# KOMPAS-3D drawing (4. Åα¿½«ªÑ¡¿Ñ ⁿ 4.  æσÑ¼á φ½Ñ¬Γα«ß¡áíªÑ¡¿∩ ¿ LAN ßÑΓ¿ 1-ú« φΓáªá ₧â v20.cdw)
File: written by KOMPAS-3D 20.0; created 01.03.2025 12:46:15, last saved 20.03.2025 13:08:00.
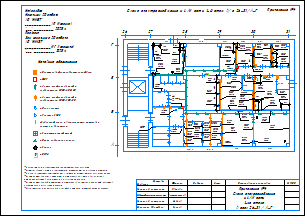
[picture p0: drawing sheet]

Sheet 1: A4, landscape

Document properties: Автор: user; Полное имя файла: \\Storage\20 Отдел\Мои документы\Крашенинников Е\ТЗ 1й этаж юг\готово\4. Приложение № 4.  Схема электроснабжения и LAN сети 1-го этажа ЮГ v20.cdw

Title block, sheet 1: scale: 1:1; Количество листов документа: 1; Форматы листов документа: A4

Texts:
  Блок №2
  Блок №3
  Блок №1
  Блок №6
  Блок №5
  Блок №4
  *В кабинете 101а произвести замену электрических кабелей
  *Перфорированные лотки с разделителем монтируются за подвесныи потолком
  *В к. 103/1 остаются существующие розетки, меняются только кабельные линии
  *Места установки камер уточнять у сотрудников 18 отдела, все камерные
  UTP линии завести в кабинет 101а с необходимым запасом
  *Место установки СКУД уточнять у сотрудников 18 отдела, 1 линию UTP завести в
  кабинет 101а с необходимым запасом
  *Вводной кабель ВВГ нг(А)LS 5х50 для ШСР 1 этаж Юг, монтаж силами заказчика
  Утверждаю
  Начальник 20 отдела
  АО "НИИЭТ"
  Зам. начальника 20 отдела
  Схема электроснабжения и LAN сети 1-й этаж в/о 26-31/А-Г
  Приложение №4
  Составил
  Фамилия
  Подпись
  Дата
  Наименование планировки
  Инженер 2 категории
  Иванова
  Схема элекроснабжения
  и LAN сети
  в осях 26-31 / А-Г
  Ведущий инженер-энергетик
  Крашенинников
  Дибров
  Начальник 18 отдела
  Крюков
  розетка
  Блок №3,4
  ШСР
  Условные обозначения:
  - Пластиковый распределительный бокс
  - ШСР
  - Лоток перфорированный с
  разделителем 3000х200х50
  разделителем 3000х100х50
  - Блок розеток
  - Розетка 380В
  -Кабельный канал с возможностью установки
  розеток с делителем
  - Коммутационный шкаф
  - Опуск кабельного канала
  - Камера
  - СКУД
  Блок №3.
  Блок №7
  розетка накл.
  роз.внутр.
  СКУД
  боксы
  cacwq
  Стили документа
  Без основной надписи.
Dimensions and other numbers on the sheet: 101; 101а; 102а; 102б; 102в; 103; 101б; 101г; 101в; 103а; 103б; 103в; 1x2я LAN; 4х220В; 2х220В; 1х2я LAN; 2x220В; 4x220В; 1-го этажа; 1х380В 25А; 1х220В 32А; 103/1; 103/2; 500; 2000; 1000; 1350; 8х220В; 2х2я LAN; 1140; 600; 1 этаж; 1-1 этаж; 27; 28; 29; 30; 31; 26; 942; 2131; 2156; 1082; 250; 952; 460; 1200; 4х220в; 800; 4х220; 1х1я LAN; 1х220В; 1:1; 1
